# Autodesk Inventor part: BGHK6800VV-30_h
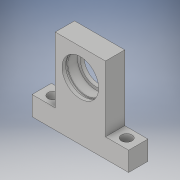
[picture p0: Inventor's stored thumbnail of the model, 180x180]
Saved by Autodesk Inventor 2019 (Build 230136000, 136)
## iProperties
Created: 2022-11
Part Number: BGHK6800VV-30_h
Material: Generic
Catalog Web Link: www.cadenas.de
Description: BGHKB, BGHK, BGHKA, BGHKSA, BGHKS_housing-Bearings with Housings - T-Shaped - h Selectable
Vendor: MISUMI
Document SubType Name: Modeling
Designer: psAdmin
Manufacturer: MISUMI
Mass: 10.6593 g
Surface Area: 51.3935 cm^2
Volume: 10.6593 cm^3
Density: 1 g/cm^3
Appearance: PSOLRGB-175-175-175
Category: PARTsolutions
Company: MISUMI
Title: BGHK6800VV-30
Author: Cadenas PARTsolutions
Comments: Bearings with Housings - T-Shaped - h Selectable
PSOL_IDENT_0: {$CADENAS_DATA/23d-libs/misumi/metric/12_bearing_holders/bghkb/bghkb_housing.prj},237 {VTYP=3D},{NB=
PSOL_IDENT_1: BGHK6800VV-30_h},{LINA=BGHK6800VV-30},{NN=BGHKB, BGHK, BGHKA, BGHKSA, BGHKS_housing},{DATE=30.03.201
PSOL_IDENT_2: 8 01:48:21},{GEOMDATE=23.03.2015 00:00:00},{VERSION=},{LINEID=300},{WBVAR=MATB,MATH,STH,SEAL,HH,ALT1
PSOL_IDENT_3: ,ALT2},{WBNUMERIC=HH}  {NB=BGHK6800VV-30_h},{LINA=BGHK6800VV-30},{KT=DUMMY},{PN=BGHK6800VV-30},{TYPE=
PSOL_IDENT_4: BGHK},{MATB=S},{MATBALG='S','Steel','SS','Stainless Steel'},{MATH=S45C},{MATHALG='S45C','1045 Carbon
PSOL_IDENT_5: Steel','2017AA','2017 Aluminum Alloy'},{STH=ENP},{STHALG='BO','Black Oxide','ENP','Electroless Nick
PSOL_IDENT_6: el Plating'},{ARR=304 Stainless Steel},{ARR3D=-S},{BN=6800},{SEAL=VV},{SEALALG='ZZ','Double Shielded'
PSOL_IDENT_7: ,'VV','Non-Contact Sealed Rubber Seal','DD','Contact Sealed Rubber Seal'},{HH=30},{HHALG=[20,25,30]}
PSOL_IDENT_8: ,{DD=10},{D=19},{DD2=20},{MM=1.15},{DDHH=16},{B=5},{LL1=2},{H=44},{H2=14},{L=50},{L1=38.0},{L2=26},{
PSOL_IDENT_9: T=10},{S=10},{DD1=5.5},{ALT1=},{ALT2=}
NB: BGHK6800VV-30_h
NN: BGHKB, BGHK, BGHKA, BGHKSA, BGHKS_housing
NT: Bearings with Housings - T-Shaped - h Selectable
NBSYN: $PN._h
LINA: BGHK6800VV-30
CATALOG: Misumi
PN: BGHK6800VV-30
MATB: Steel
MATH: 1045 Carbon Steel
STH: Electroless Nickel Plating
ARR: 304 Stainless Steel
BN: 6800
SEAL: Non-Contact Sealed Rubber Seal
HH: 30
DD: 10
D: 19
DDHH: 16
B: 5
LL1: 2
H: 44
L: 50
L1: 38
L2: 26
T: 10
S: 10
DD1: 5.5
ALT1: Bearings, Retaining Rings Assembled
ALT2: w/o KCC (C2 Chamfer)
SUPPLIER: MISUMI
ARTICLENO: BGHK6800VV-30_h
BOMINFO: BGHK6800VV-30
CREATOR: CADENAS GmbH
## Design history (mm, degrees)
sketch "Sketch_1"
  geometry: L1 (-25, -20)-(-25, -30); L2 (-25, -30)-(25, -30); L3 (25, -30)-(25, -20); L4 (25, -20)-(13, -20); L5 (13, -20)-(13, 14); L6 (13, 14)-(-13, 14); L7 (-13, 14)-(-13, -20); L8 (-13, -20)-(-25, -20)
  constraints: 16 end point
extrude "Extrusion1" join sketch "Sketch_1" stored distance "d0" = 10; taper "d1" = 0 deg
sketch "Sketch2"
  geometry: 1 further point
hole "Hole1" sketch "Sketch2" at (0, 0) diameter "d2" = 16; stored, may be unused: countersink angle "d6" = 90 deg, drill point angle "d8" = 0 deg; dims "d3" = 6, "d4" = 19, "d5" = 8, "d7" = 10
sketch "Sketch3"
  geometry: 1 further point
hole "Hole2" sketch "Sketch3" at (6, -5) diameter "d9" = 5.5; stored, may be unused: countersink angle "d13" = 90 deg, drill point angle "d15" = 0 deg; dims "d10" = 6, "d11" = 4, "d12" = 2, "d14" = 10
sketch "Sketch4"
  geometry: 1 further point
hole "Hole3" sketch "Sketch4" at (44, -5) diameter "d16" = 5.5; stored, may be unused: countersink angle "d20" = 90 deg, drill point angle "d22" = 0 deg; dims "d17" = 6, "d18" = 4, "d19" = 2, "d21" = 10
sketch "Sketch_4"
  geometry: L1 (-2, 0)-(-3.15, 0); L2 (-3.15, 0)-(-3.15, 10); L3 (-3.15, 10)-(-2, 10); L4 (-2, 10)-(-2, 0); L5 (-2, 0)-(-3.15, 0)
  constraints: 10 end point
revolve "Revolution1" sketch "Sketch_4" stored, may be unused: angle "d23" = 360 deg
node "housing_to_dummy_XY"
node "housing_to_dummy_YZ"
node "housing_to_dummy_ZX"
node "housing_to_dummy_X"
node "housing_to_dummy_Y"
node "housing_to_dummy_Z"
node "housing_to_dummy_Center"
node "to_bearing_XY"
node "to_bearing_YZ"
node "to_bearing_ZX"
node "to_bearing_X"
node "to_bearing_Y"
node "to_bearing_Z"
node "to_bearing_Center"
node "to_rring_XY"
node "to_rring_YZ"
node "to_rring_ZX"
node "to_rring_X"
node "to_rring_Y"
node "to_rring_Z"
node "to_rring_Center"
body "Solid1"
other parameters: "d24" = 0, "d25" = 0
